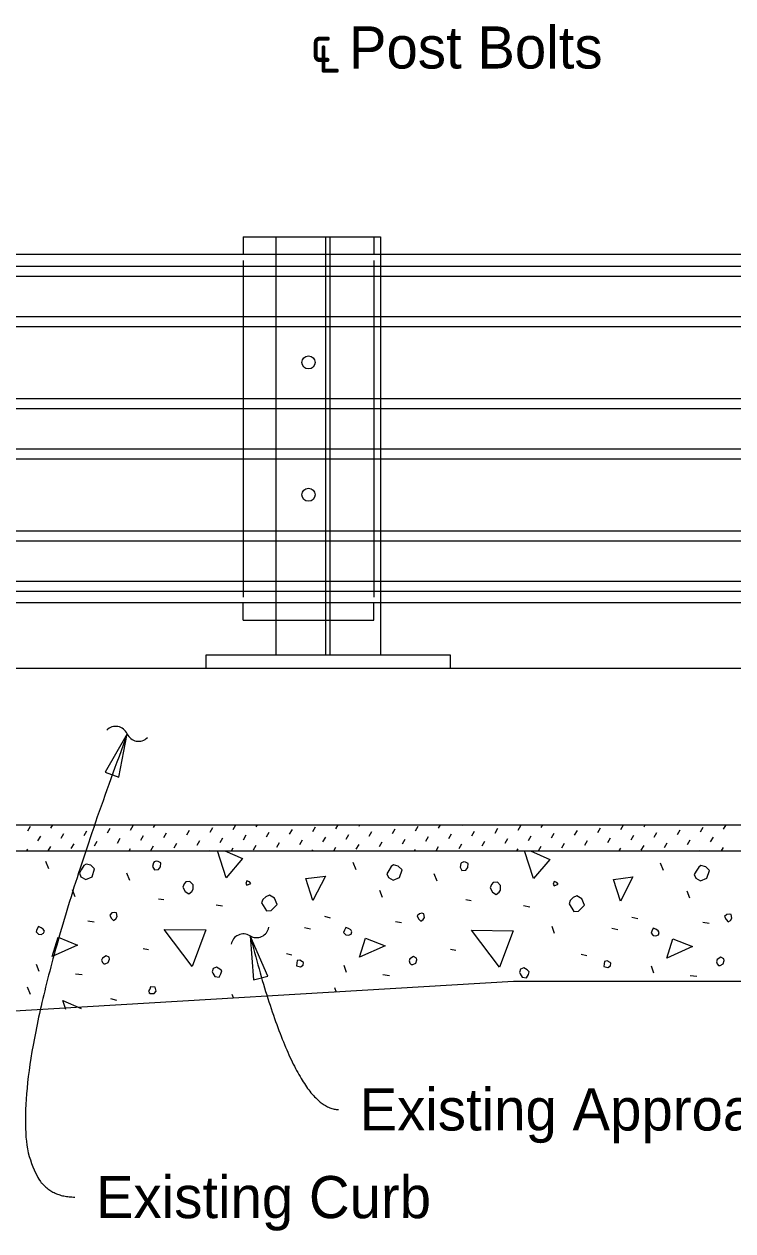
# Model space of a CAD drawing. Extents: x 21665 to 21741.5, y 56121.9 to 56164.2.
# Drawn here: x 21702.01 to 21705.4, y 56139.73 to 56145.5 of the extents above; entities that cross this region are included whole.
import ezdxf

# ---------------------------------------------------------------- set-up
doc = ezdxf.new("R2010")
doc.units = 0
for name, color, linetype in [('Dimension', 7, 'Continuous'), ('ExistSuperStruct', 7, 'Continuous'), ('Miscellaneous', 7, 'Continuous'), ('SteelMisc', 7, 'Continuous'), ('SteelMisc_h', 7, 'Continuous'), ('TextStructures', 7, 'Continuous')]:
    doc.layers.add(name, color=color, linetype=linetype)

msp = doc.modelspace()

# ---------------------------------------------------------------- linework, layer by layer
at = {"layer": 'Dimension'}
for points in [[(21702.503, 56142.1038), (21702.3972, 56141.921), (21702.4633, 56141.8963)], [(21703.0905, 56141.1377), (21703.1076, 56140.9271), (21703.176, 56140.9445)]]:
    msp.add_lwpolyline(points, close=True, dxfattribs=at)
for centre, start, end in [((21702.4477, 56142.08), 23.71863, 135.44585), ((21702.5569, 56142.1279), 203.71863, 315.44585), ((21703.1214, 56141.1882), 238.43842, 350.16564), ((21703.059, 56141.0866), 58.43842, 170.16564)]:
    msp.add_arc(centre, 0.0596, start, end, dxfattribs=at)
for points in [[(21702.503, 56142.1038), (21701.676, 56139.8872), (21702.2524, 56139.8872)], [(21703.0909, 56141.1376), (21703.3021, 56140.3064), (21703.5134, 56140.3064)]]:
    msp.add_open_spline(points, degree=2, dxfattribs=at)
at = {"layer": 'ExistSuperStruct'}
for p, q in [((21699.1315, 56142.4186), (21707.1339, 56142.4186)), ((21699.1314, 56141.6687), (21711.5431, 56141.6687)), ((21699.1314, 56141.5437), (21711.5431, 56141.5437)), ((21704.3514, 56140.9187), (21700.1315, 56140.6687)), ((21711.5431, 56140.9187), (21704.3514, 56140.9187))]:
    msp.add_line(p, q, dxfattribs=at)
at = {"layer": 'Miscellaneous'}
for p, q in [((21703.0576, 56144.4811), (21703.6826, 56144.4811)), ((21703.0576, 56144.4811), (21703.0576, 56144.3977)), ((21703.6826, 56144.4811), (21703.6826, 56144.3977)), ((21703.0576, 56144.3692), (21703.0576, 56142.7573)), ((21703.6826, 56144.3692), (21703.6826, 56142.7573)), ((21703.0576, 56142.6477), (21703.0576, 56142.7311)), ((21703.6826, 56142.6477), (21703.6826, 56142.7311)), ((21703.0576, 56142.6477), (21703.6826, 56142.6477)), ((21702.027, 56141.6402), (21702.04, 56141.6626)), ((21702.1376, 56141.6531), (21702.1467, 56141.6687)), ((21702.1865, 56141.6043), (21702.1994, 56141.6267)), ((21702.2483, 56141.6661), (21702.2498, 56141.6687)), ((21702.2971, 56141.6173), (21702.3101, 56141.6397)), ((21702.4077, 56141.6302), (21702.4207, 56141.6526)), ((21702.5184, 56141.6432), (21702.5313, 56141.6656)), ((21702.629, 56141.6562), (21702.6363, 56141.6687)), ((21702.6778, 56141.6073), (21702.6908, 56141.6297)), ((21702.7885, 56141.6203), (21702.8014, 56141.6427)), ((21702.8991, 56141.6332), (21702.9121, 56141.6556)), ((21703.0097, 56141.6462), (21703.0227, 56141.6686)), ((21703.1204, 56141.6592), (21703.1259, 56141.6687)), ((21703.1692, 56141.6103), (21703.1822, 56141.6327)), ((21703.2798, 56141.6233), (21703.2928, 56141.6457)), ((21703.3905, 56141.6363), (21703.4034, 56141.6587)), ((21703.5011, 56141.6492), (21703.5124, 56141.6687)), ((21703.5499, 56141.6004), (21703.5629, 56141.6228)), ((21703.6117, 56141.6622), (21703.6155, 56141.6687)), ((21703.6606, 56141.6134), (21703.6735, 56141.6357)), ((21703.7712, 56141.6263), (21703.7842, 56141.6487)), ((21703.8818, 56141.6393), (21703.8948, 56141.6617)), ((21703.9925, 56141.6522), (21704.002, 56141.6687)), ((21704.0413, 56141.6034), (21704.0543, 56141.6258)), ((21704.1031, 56141.6652), (21704.1051, 56141.6687)), ((21704.1519, 56141.6164), (21704.1649, 56141.6388)), ((21704.2626, 56141.6293), (21704.2755, 56141.6517)), ((21704.3732, 56141.6423), (21704.3862, 56141.6647)), ((21704.4838, 56141.6553), (21704.4916, 56141.6687)), ((21704.5327, 56141.6064), (21704.5456, 56141.6288)), ((21704.5945, 56141.6682), (21704.5948, 56141.6687)), ((21704.6433, 56141.6194), (21704.6563, 56141.6418)), ((21704.7539, 56141.6324), (21704.7669, 56141.6548)), ((21704.8646, 56141.6453), (21704.8775, 56141.6677)), ((21704.9752, 56141.6583), (21704.9812, 56141.6687)), ((21705.024, 56141.6095), (21705.037, 56141.6318)), ((21705.1347, 56141.6224), (21705.1476, 56141.6448)), ((21705.2453, 56141.6354), (21705.2583, 56141.6578)), ((21705.3559, 56141.6483), (21705.3677, 56141.6687)), ((21702.0758, 56141.5913), (21702.0888, 56141.6137)), ((21702.1253, 56141.5437), (21702.1376, 56141.5649)), ((21702.2353, 56141.5555), (21702.2483, 56141.5779)), ((21702.3459, 56141.5684), (21702.3589, 56141.5908)), ((21702.4566, 56141.5814), (21702.4695, 56141.6038)), ((21702.5672, 56141.5944), (21702.5802, 56141.6167)), ((21702.616, 56141.5455), (21702.629, 56141.5679)), ((21702.7267, 56141.5585), (21702.7396, 56141.5809)), ((21702.8373, 56141.5714), (21702.8503, 56141.5938)), ((21702.9479, 56141.5844), (21702.9609, 56141.6068)), ((21703.0586, 56141.5974), (21703.0715, 56141.6198)), ((21703.1074, 56141.5485), (21703.1204, 56141.5709)), ((21703.218, 56141.5615), (21703.231, 56141.5839)), ((21703.3287, 56141.5745), (21703.3416, 56141.5969)), ((21703.4393, 56141.5874), (21703.4523, 56141.6098)), ((21703.5988, 56141.5516), (21703.6117, 56141.5739)), ((21703.7094, 56141.5645), (21703.7224, 56141.5869)), ((21703.82, 56141.5775), (21703.833, 56141.5999)), ((21703.9307, 56141.5904), (21703.9436, 56141.6128)), ((21704.0901, 56141.5546), (21704.1031, 56141.577)), ((21704.2008, 56141.5675), (21704.2137, 56141.5899)), ((21704.3114, 56141.5805), (21704.3244, 56141.6029)), ((21704.422, 56141.5935), (21704.435, 56141.6159)), ((21704.4709, 56141.5446), (21704.4838, 56141.567)), ((21704.5815, 56141.5576), (21704.5945, 56141.58)), ((21704.6921, 56141.5706), (21704.7051, 56141.593)), ((21704.8028, 56141.5835), (21704.8157, 56141.6059)), ((21704.9134, 56141.5965), (21704.9264, 56141.6189)), ((21704.9622, 56141.5477), (21704.9752, 56141.57)), ((21705.0729, 56141.5606), (21705.0858, 56141.583)), ((21705.1835, 56141.5736), (21705.1965, 56141.596)), ((21705.2941, 56141.5865), (21705.3071, 56141.6089)), ((21702.0222, 56141.5437), (21702.027, 56141.5519)), ((21702.5118, 56141.5437), (21702.5184, 56141.5549)), ((21702.8983, 56141.5437), (21702.8991, 56141.545)), ((21703.0015, 56141.5437), (21703.0097, 56141.558)), ((21703.3879, 56141.5437), (21703.3905, 56141.548)), ((21703.4911, 56141.5437), (21703.5011, 56141.561)), ((21703.8776, 56141.5437), (21703.8818, 56141.551)), ((21703.9807, 56141.5437), (21703.9925, 56141.564)), ((21704.3672, 56141.5437), (21704.3732, 56141.5541)), ((21704.7537, 56141.5437), (21704.7539, 56141.5441)), ((21704.8568, 56141.5437), (21704.8646, 56141.5571)), ((21705.2433, 56141.5437), (21705.2453, 56141.5471)), ((21705.3464, 56141.5437), (21705.3559, 56141.5601)), ((21702.1277, 56141.4571), (21702.1135, 56141.4924)), ((21703.5983, 56141.4535), (21703.5841, 56141.4889)), ((21705.0689, 56141.45), (21705.0548, 56141.4854)), ((21702.5147, 56141.4024), (21702.5006, 56141.4377)), ((21703.9854, 56141.3988), (21703.9712, 56141.4342)), ((21702.2532, 56141.3245), (21702.2408, 56141.3581)), ((21703.7238, 56141.321), (21703.7114, 56141.3546)), ((21705.1944, 56141.3174), (21705.1821, 56141.351)), ((21702.6526, 56141.314), (21702.6774, 56141.3104)), ((21702.9284, 56141.2857), (21702.9584, 56141.2804)), ((21704.1232, 56141.3104), (21704.148, 56141.3069)), ((21704.399, 56141.2821), (21704.4291, 56141.2768)), ((21703.4463, 56141.2308), (21703.4745, 56141.2237)), ((21704.9169, 56141.2273), (21704.9452, 56141.2202)), ((21702.315, 56141.2097), (21702.345, 56141.2044)), ((21703.3509, 56141.1779), (21703.3792, 56141.1708)), ((21703.7856, 56141.2061), (21703.8157, 56141.2008)), ((21704.5475, 56141.1478), (21704.5351, 56141.1814)), ((21704.8215, 56141.1743), (21704.8498, 56141.1672)), ((21705.2562, 56141.2026), (21705.2863, 56141.1973)), ((21702.5784, 56141.0771), (21702.6049, 56141.0718)), ((21703.2641, 56141.0523), (21703.2906, 56141.047)), ((21704.049, 56141.0736), (21704.0755, 56141.0682)), ((21704.6748, 56141.0488), (21704.7013, 56141.0435)), ((21702.0817, 56140.9658), (21702.0693, 56140.9994)), ((21703.5523, 56140.9623), (21703.54, 56140.9958)), ((21705.023, 56140.9587), (21705.0106, 56140.9923)), ((21702.2549, 56140.9551), (21702.2867, 56140.9516)), ((21703.7255, 56140.9516), (21703.7573, 56140.948)), ((21705.1961, 56140.948), (21705.2279, 56140.9445)), ((21702.0393, 56140.8562), (21702.0251, 56140.8915)), ((21703.5047, 56140.8658), (21703.4958, 56140.888)), ((21702.4228, 56140.8367), (21702.4511, 56140.8296)), ((21703.0106, 56140.8413), (21703.0046, 56140.8561))]:
    msp.add_line(p, q, dxfattribs=at)
for points in [[(21702.9761, 56141.4147), (21702.9342, 56141.5437)], [(21702.9691, 56141.5437), (21703.0539, 56141.5067), (21702.9761, 56141.4147)], [(21704.4467, 56141.4112), (21704.4037, 56141.5437)], [(21704.4317, 56141.5437), (21704.5245, 56141.5031), (21704.4467, 56141.4112)], [(21702.2814, 56141.42), (21702.3044, 56141.4076), (21702.3345, 56141.42), (21702.3469, 56141.4571), (21702.3292, 56141.4748), (21702.3062, 56141.4801), (21702.2956, 56141.473), (21702.2832, 56141.4535), (21702.2744, 56141.4376), (21702.2814, 56141.42)], [(21702.6243, 56141.4695), (21702.6332, 56141.4536), (21702.6526, 56141.4554), (21702.6614, 56141.4678), (21702.6632, 56141.4872), (21702.6508, 56141.4925), (21702.642, 56141.4943), (21702.6314, 56141.4907), (21702.6279, 56141.4872), (21702.6243, 56141.4695)], [(21703.7521, 56141.4164), (21703.7751, 56141.4041), (21703.8051, 56141.4164), (21703.8175, 56141.4535), (21703.7998, 56141.4712), (21703.7768, 56141.4765), (21703.7662, 56141.4695), (21703.7539, 56141.45), (21703.745, 56141.4341), (21703.7521, 56141.4164)], [(21704.095, 56141.466), (21704.1038, 56141.4501), (21704.1232, 56141.4519), (21704.1321, 56141.4642), (21704.1338, 56141.4837), (21704.1215, 56141.489), (21704.1126, 56141.4907), (21704.102, 56141.4872), (21704.0985, 56141.4837), (21704.095, 56141.466)], [(21705.2227, 56141.4129), (21705.2457, 56141.4005), (21705.2758, 56141.4129), (21705.2881, 56141.45), (21705.2704, 56141.4677), (21705.2475, 56141.473), (21705.2369, 56141.4659), (21705.2245, 56141.4465), (21705.2156, 56141.4306), (21705.2227, 56141.4129)], [(21702.7693, 56141.3705), (21702.7799, 56141.3493), (21702.7976, 56141.3387), (21702.8117, 56141.3493), (21702.8188, 56141.3599), (21702.8188, 56141.3811), (21702.8029, 56141.3971), (21702.7834, 56141.3953), (21702.7746, 56141.3864), (21702.7693, 56141.3705)], [(21703.0751, 56141.3794), (21703.0945, 56141.3882), (21703.0875, 56141.3953), (21703.0751, 56141.4006), (21703.0698, 56141.3882), (21703.0751, 56141.3794)], [(21703.3915, 56141.3068), (21703.3579, 56141.4111), (21703.4516, 56141.4235), (21703.3915, 56141.3068)], [(21704.2399, 56141.367), (21704.2505, 56141.3458), (21704.2682, 56141.3352), (21704.2823, 56141.3458), (21704.2894, 56141.3564), (21704.2894, 56141.3776), (21704.2735, 56141.3935), (21704.2541, 56141.3918), (21704.2452, 56141.3829), (21704.2399, 56141.367)], [(21704.5457, 56141.3758), (21704.5652, 56141.3847), (21704.5581, 56141.3918), (21704.5457, 56141.3971), (21704.5404, 56141.3847), (21704.5457, 56141.3758)], [(21704.8621, 56141.3033), (21704.8285, 56141.4076), (21704.9222, 56141.42), (21704.8621, 56141.3033)], [(21703.1458, 56141.2945), (21703.1688, 56141.2574), (21703.1918, 56141.2592), (21703.2006, 56141.268), (21703.2201, 56141.2875), (21703.2077, 56141.3175), (21703.1829, 56141.3316), (21703.1653, 56141.3246), (21703.1511, 56141.3104), (21703.1458, 56141.2945)], [(21704.6164, 56141.291), (21704.6394, 56141.2539), (21704.6624, 56141.2556), (21704.6712, 56141.2645), (21704.6907, 56141.2839), (21704.6783, 56141.314), (21704.6536, 56141.3281), (21704.6359, 56141.321), (21704.6218, 56141.3069), (21704.6164, 56141.291)], [(21702.4263, 56141.222), (21702.4369, 56141.2114), (21702.4475, 56141.2185), (21702.4546, 56141.2291), (21702.4511, 56141.2468), (21702.4422, 56141.2486), (21702.4299, 56141.2468), (21702.4193, 56141.2362), (21702.4263, 56141.222)], [(21703.897, 56141.2185), (21703.9076, 56141.2079), (21703.9182, 56141.215), (21703.9253, 56141.2256), (21703.9217, 56141.2433), (21703.9129, 56141.245), (21703.9005, 56141.2433), (21703.8899, 56141.2327), (21703.897, 56141.2185)], [(21705.3676, 56141.215), (21705.3782, 56141.2044), (21705.3888, 56141.2114), (21705.3959, 56141.222), (21705.3924, 56141.2397), (21705.3835, 56141.2415), (21705.3711, 56141.2397), (21705.3605, 56141.2291), (21705.3676, 56141.215)], [(21702.0782, 56141.146), (21702.0905, 56141.1442), (21702.1029, 56141.1495), (21702.1064, 56141.1601), (21702.1011, 56141.1689), (21702.0905, 56141.176), (21702.0782, 56141.1813), (21702.0711, 56141.1672), (21702.0675, 56141.1566), (21702.0782, 56141.146)], [(21702.8135, 56140.9905), (21702.6791, 56141.1672), (21702.8789, 56141.1655), (21702.8135, 56140.9905)], [(21703.5488, 56141.1424), (21703.5612, 56141.1407), (21703.5735, 56141.146), (21703.5771, 56141.1566), (21703.5718, 56141.1654), (21703.5612, 56141.1725), (21703.5488, 56141.1778), (21703.5417, 56141.1636), (21703.5382, 56141.153), (21703.5488, 56141.1424)], [(21704.2841, 56140.9869), (21704.1498, 56141.1637), (21704.3495, 56141.1619), (21704.2841, 56140.9869)], [(21705.0194, 56141.1389), (21705.0318, 56141.1371), (21705.0442, 56141.1424), (21705.0477, 56141.153), (21705.0424, 56141.1619), (21705.0318, 56141.1689), (21705.0194, 56141.1742), (21705.0124, 56141.1601), (21705.0088, 56141.1495), (21705.0194, 56141.1389)], [(21702.1435, 56141.0382), (21702.1718, 56141.1301), (21702.2655, 56141.093), (21702.1435, 56141.0382)], [(21703.6141, 56141.0347), (21703.6424, 56141.1266), (21703.7361, 56141.0895), (21703.6141, 56141.0347)], [(21705.0848, 56141.0311), (21705.113, 56141.1231), (21705.2067, 56141.0859), (21705.0848, 56141.0311)], [(21702.391, 56141.0028), (21702.398, 56141.0028), (21702.4122, 56141.0099), (21702.4175, 56141.0258), (21702.4157, 56141.0347), (21702.4016, 56141.0417), (21702.3839, 56141.0311), (21702.3804, 56141.0205), (21702.3839, 56141.0099), (21702.391, 56141.0028)], [(21703.312, 56140.994), (21703.3314, 56140.9887), (21703.3438, 56140.9975), (21703.3456, 56141.0099), (21703.342, 56141.0134), (21703.3279, 56141.0205), (21703.3155, 56141.0188), (21703.3138, 56141.0064), (21703.312, 56140.994)], [(21703.8616, 56140.9993), (21703.8687, 56140.9993), (21703.8828, 56141.0064), (21703.8881, 56141.0223), (21703.8864, 56141.0311), (21703.8722, 56141.0382), (21703.8545, 56141.0276), (21703.851, 56141.017), (21703.8545, 56141.0064), (21703.8616, 56140.9993)], [(21704.7826, 56140.9905), (21704.8021, 56140.9852), (21704.8144, 56140.994), (21704.8162, 56141.0064), (21704.8127, 56141.0099), (21704.7985, 56141.017), (21704.7862, 56141.0152), (21704.7844, 56141.0028), (21704.7826, 56140.9905)], [(21705.3322, 56140.9958), (21705.3393, 56140.9958), (21705.3535, 56141.0028), (21705.3588, 56141.0188), (21705.357, 56141.0276), (21705.3429, 56141.0347), (21705.3252, 56141.0241), (21705.3216, 56141.0134), (21705.3252, 56141.0028), (21705.3322, 56140.9958)], [(21702.9125, 56140.9586), (21702.9213, 56140.9427), (21702.9425, 56140.9392), (21702.9514, 56140.9551), (21702.9549, 56140.9693), (21702.9461, 56140.9781), (21702.9301, 56140.9869), (21702.9142, 56140.9816), (21702.9089, 56140.9657), (21702.9125, 56140.9586)], [(21704.3831, 56140.9551), (21704.3919, 56140.9392), (21704.4132, 56140.9357), (21704.422, 56140.9516), (21704.4255, 56140.9657), (21704.4167, 56140.9746), (21704.4008, 56140.9834), (21704.3849, 56140.9781), (21704.3796, 56140.9622), (21704.3831, 56140.9551)], [(21702.6102, 56140.8614), (21702.6314, 56140.8614), (21702.642, 56140.872), (21702.6367, 56140.8915), (21702.6137, 56140.8932), (21702.6102, 56140.8826), (21702.6049, 56140.8738), (21702.6102, 56140.8614), (21702.6066, 56140.865)], [(21702.2089, 56140.7848), (21702.1948, 56140.8279), (21702.283, 56140.7894)]]:
    msp.add_lwpolyline(points, dxfattribs=at)
at = {"layer": 'SteelMisc'}
for p, q in [((21703.2138, 56144.4811), (21703.7138, 56144.4811)), ((21703.2138, 56144.4811), (21703.2138, 56144.3977)), ((21703.7138, 56144.4811), (21703.7138, 56144.3977)), ((21705.8005, 56144.3977), (21695.8861, 56144.3977)), ((21695.8861, 56144.3422), (21705.8005, 56144.3422)), ((21695.8861, 56144.294), (21705.8005, 56144.294)), ((21695.8861, 56144.1012), (21705.8005, 56144.1012)), ((21695.8861, 56144.053), (21705.8005, 56144.053)), ((21695.8861, 56143.709), (21705.8005, 56143.709)), ((21695.8861, 56143.6608), (21705.8005, 56143.6608)), ((21695.8861, 56143.468), (21705.8005, 56143.468)), ((21695.8861, 56143.4198), (21705.8005, 56143.4198)), ((21695.8861, 56143.0759), (21705.8005, 56143.0759)), ((21695.8861, 56143.0276), (21705.8005, 56143.0276)), ((21695.8861, 56142.8348), (21705.8005, 56142.8348)), ((21695.8861, 56142.7866), (21705.8005, 56142.7866)), ((21705.8005, 56142.7311), (21695.8861, 56142.7311)), ((21703.2138, 56142.7311), (21703.2138, 56142.4811)), ((21703.7138, 56142.7311), (21703.7138, 56142.4811)), ((21702.8805, 56142.4811), (21704.0472, 56142.4811)), ((21702.8805, 56142.4186), (21702.8805, 56142.4811)), ((21703.2138, 56142.4811), (21703.7138, 56142.4811)), ((21704.0472, 56142.4811), (21704.0472, 56142.4186)), ((21702.8805, 56142.4186), (21704.0472, 56142.4186))]:
    msp.add_line(p, q, dxfattribs=at)
for centre in [(21703.3701, 56143.881), (21703.3701, 56143.2479)]:
    msp.add_circle(centre, 0.0312, dxfattribs=at)
at = {"layer": 'SteelMisc_h'}
for p, q in [((21703.4534, 56142.4811), (21703.4534, 56144.4811)), ((21703.4742, 56142.4811), (21703.4742, 56144.4811)), ((21703.2138, 56144.3977), (21703.2138, 56142.7311)), ((21703.7138, 56144.3977), (21703.7138, 56142.7311))]:
    msp.add_line(p, q, dxfattribs=at)

# ---------------------------------------------------------------- texts
at = {"layer": 'TextStructures'}
for s, p in [('℄ Post Bolts', (21703.3791, 56145.2873)), ('Existing Approach Slab', (21703.6143, 56140.2058)), ('Existing Curb', (21702.3532, 56139.7864))]:
    msp.add_text(s, height=0.2016, dxfattribs=at).set_placement(p)

doc.saveas('drawing.dxf')
